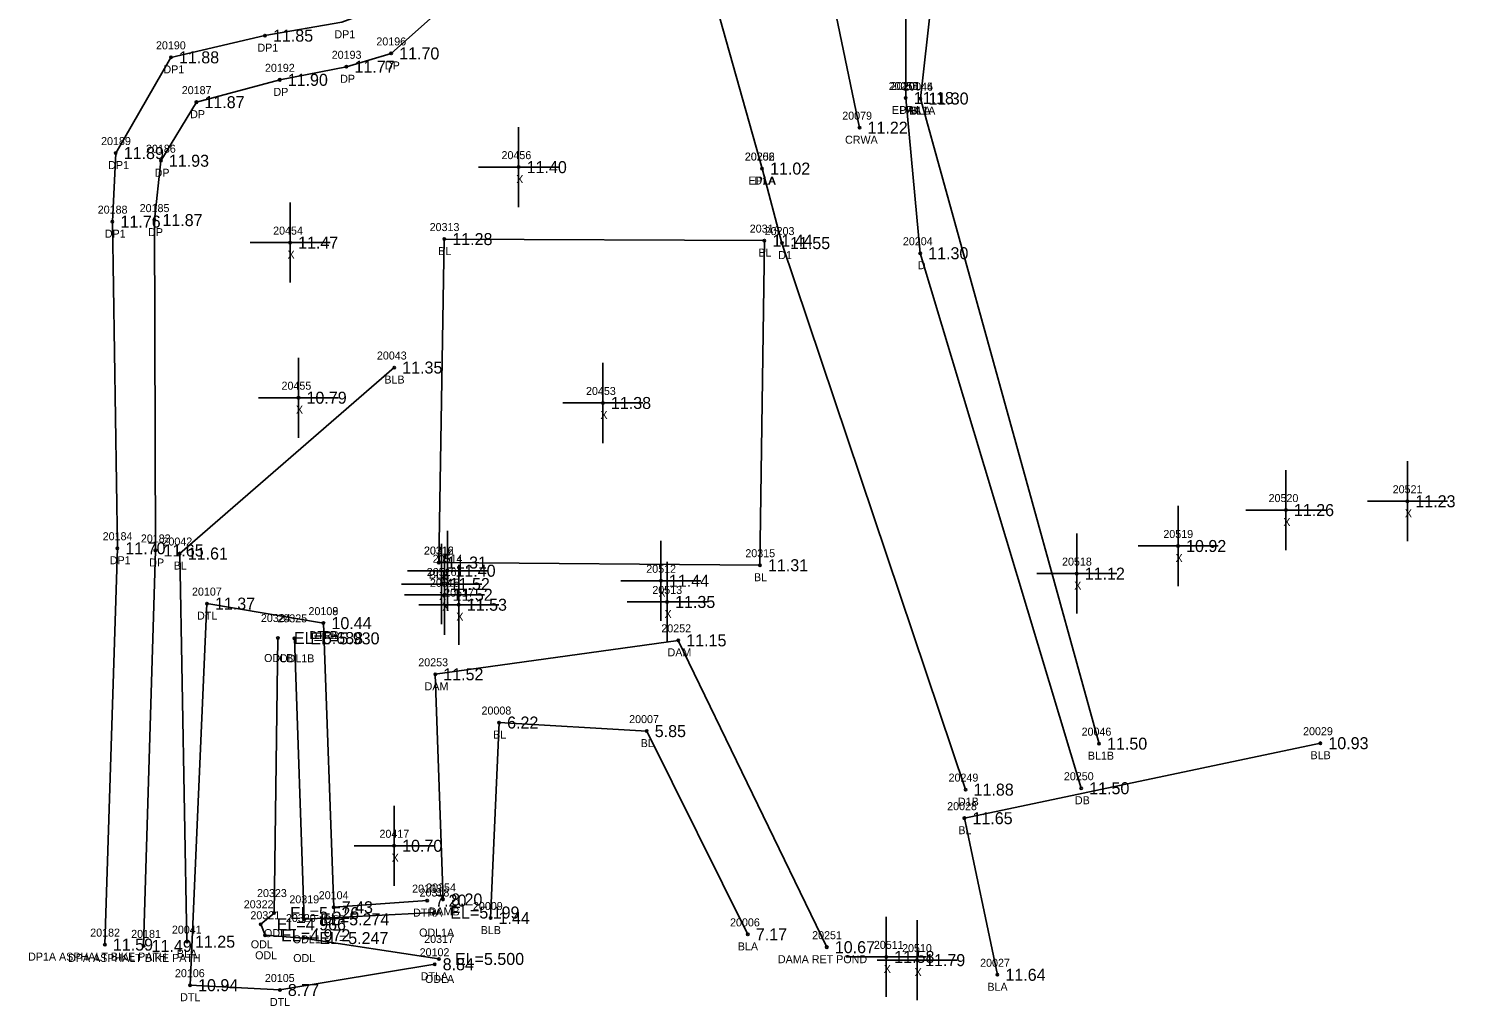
# Model space of a CAD drawing. Extents: x 2072302 to 2072980, y 127650 to 129736.
# Drawn here: x 2072679.9 to 2072860.8, y 128232.2 to 128354.3 of the extents above; entities that cross this region are included whole.
import ezdxf

# ---------------------------------------------------------------- set-up
doc = ezdxf.new("R2010")
doc.units = 0
for name, color, linetype in [('RD_DTM_BkLn1', 7, 'Continuous'), ('RD_DTM_BkLn_txCode', 7, 'Continuous'), ('RD_EX_Dam', 7, 'Continuous'), ('RD_EX_Dam_txCode', 7, 'Continuous'), ('RD_EX_Driveway', 7, 'Continuous'), ('RD_EX_Driveway_txCode', 7, 'Continuous'), ('RD_EX_H2O', 7, 'Continuous'), ('RD_EX_H2O_txCode', 7, 'Continuous'), ('RD_EX_Misc', 7, 'Continuous'), ('RD_EX_Misc_txCode', 7, 'Continuous'), ('RD_EX_Road', 7, 'Continuous'), ('RD_EX_Road_txCode', 7, 'Continuous'), ('RD_EX_TX_Dam_ELEV', 7, 'Continuous'), ('RD_EX_TX_Driveway_ELEV', 7, 'Continuous'), ('RD_EX_TX_H2O_ELEV', 7, 'Continuous'), ('RD_EX_TX_Misc_ELEV', 7, 'Continuous'), ('RD_EX_TX_Road_ELEV', 7, 'Continuous'), ('RD_HC_Survey_ELEV', 7, 'Continuous'), ('RD_HC_Survey_txCode', 7, 'Continuous'), ('RD_SMD_Locator', 7, 'Continuous')]:
    doc.layers.add(name, color=color, linetype=linetype)

msp = doc.modelspace()

# ---------------------------------------------------------------- linework, layer by layer
at = {"layer": 'RD_DTM_BkLn1'}
msp.add_line((2072791.29, 128345.62), (2072813.61, 128265.01), dxfattribs=at)
for points in [[(2072783.68, 128341.98), (2072775.38, 128381.91), (2072773.13, 128410.46), (2072778.13, 128436.13), (2072789.72, 128460.89), (2072826.62, 128532.44), (2072863.13, 128603.15), (2072886.77, 128648.23), (2072893.1, 128661.91)], [(2072791.29, 128345.62), (2072800.72, 128429.53), (2072808.9, 128452.58), (2072870.32, 128568.64), (2072876.57, 128573.6), (2072916.77, 128564.68), (2072920.97, 128548.67)], [(2072731.1, 128287.64), (2072731.79, 128328.06), (2072771.79, 128327.87), (2072771.24, 128287.31), (2072731.1, 128287.64)], [(2072699.63, 128240.27), (2072698.73, 128288.77), (2072725.53, 128312.01)], [(2072769.72, 128241.18), (2072757.09, 128266.58), (2072738.64, 128267.65), (2072737.57, 128243.22)], [(2072800.91, 128236.13), (2072796.79, 128255.7), (2072841.27, 128265.07)]]:
    msp.add_lwpolyline(points, dxfattribs=at)
at = {"layer": 'RD_EX_Dam'}
msp.add_lwpolyline([(2072779.59, 128239.58), (2072761.03, 128277.92), (2072730.66, 128273.68), (2072731.64, 128245.54)], dxfattribs=at)
at = {"layer": 'RD_EX_Driveway'}
for points in [[(2072689.37, 128239.9), (2072690.93, 128289.43), (2072690.32, 128330.24), (2072690.73, 128338.81), (2072697.63, 128350.77), (2072709.38, 128353.48), (2072719, 128355.15), (2072723.52, 128356.83), (2072727.18, 128360.82), (2072729.07, 128366.04), (2072736.87, 128415.65), (2072743.44, 128446.63), (2072749.73, 128459.37), (2072755.76, 128468.63), (2072761.76, 128476.56), (2072776.61, 128495.01), (2072792.09, 128518.96), (2072805.19, 128542.59), (2072810.66, 128554.44), (2072797.46, 128551.01)], [(2072694.21, 128239.74), (2072695.7, 128289.15), (2072695.56, 128330.43), (2072696.37, 128337.85), (2072700.81, 128345.17), (2072711.22, 128347.96), (2072719.56, 128349.59), (2072725.15, 128351.26), (2072733.07, 128358.33), (2072734.19, 128365.42), (2072741.79, 128414.16), (2072748.82, 128445.27), (2072754.15, 128456.57), (2072759.92, 128465.41), (2072766.21, 128473.75), (2072780.47, 128491.8), (2072796.27, 128516), (2072809.9, 128540.1), (2072821.01, 128555.78)], [(2072789.45, 128345.69), (2072791.26, 128326.29), (2072811.38, 128259.44)], [(2072771.5, 128336.87), (2072773.99, 128327.56), (2072796.93, 128259.27)]]:
    msp.add_lwpolyline(points, dxfattribs=at)
at = {"layer": 'RD_EX_H2O'}
for points in [[(2072730.59, 128237.45), (2072711.24, 128234.23), (2072700.02, 128234.83), (2072702.13, 128282.51), (2072716.69, 128280.07)], [(2072729.65, 128245.4), (2072717.97, 128244.57), (2072716.69, 128280.07)], [(2072731.12, 128238.11), (2072714.16, 128240.72), (2072709.4, 128241.07), (2072708.85, 128242.44), (2072710.51, 128243.84), (2072710.99, 128278.21)], [(2072730.54, 128243.91), (2072714.27, 128243.06), (2072713.05, 128278.17)]]:
    msp.add_lwpolyline(points, dxfattribs=at)
at = {"layer": 'RD_EX_Misc'}
for p, q in [((2072741.08, 128332.05), (2072741.08, 128342.05)), ((2072736.08, 128337.05), (2072746.08, 128337.05)), ((2072712.52, 128322.62), (2072712.52, 128332.62)), ((2072707.52, 128327.62), (2072717.52, 128327.62)), ((2072713.57, 128303.24), (2072713.57, 128313.24)), ((2072751.61, 128302.58), (2072751.61, 128312.58)), ((2072708.57, 128308.24), (2072718.57, 128308.24)), ((2072746.61, 128307.58), (2072756.61, 128307.58)), ((2072836.96, 128289.2), (2072836.96, 128299.2)), ((2072852.14, 128290.3), (2072852.14, 128300.3)), ((2072847.14, 128295.3), (2072857.14, 128295.3)), ((2072823.49, 128284.71), (2072823.49, 128294.71)), ((2072831.96, 128294.2), (2072841.96, 128294.2)), ((2072731.46, 128279.96), (2072731.46, 128289.96)), ((2072732.18, 128281.62), (2072732.18, 128291.62)), ((2072758.86, 128280.36), (2072758.86, 128290.36)), ((2072810.82, 128281.26), (2072810.82, 128291.26)), ((2072731.82, 128278.61), (2072731.82, 128288.61)), ((2072818.49, 128289.71), (2072828.49, 128289.71)), ((2072727.18, 128286.62), (2072737.18, 128286.62)), ((2072733.6, 128277.37), (2072733.6, 128287.37)), ((2072759.63, 128277.72), (2072759.63, 128287.72)), ((2072805.82, 128286.26), (2072815.82, 128286.26)), ((2072726.46, 128284.96), (2072736.46, 128284.96)), ((2072753.86, 128285.36), (2072763.86, 128285.36)), ((2072726.82, 128283.61), (2072736.82, 128283.61)), ((2072754.63, 128282.72), (2072764.63, 128282.72)), ((2072728.6, 128282.37), (2072738.6, 128282.37)), ((2072725.52, 128247.25), (2072725.52, 128257.25)), ((2072720.52, 128252.25), (2072730.52, 128252.25)), ((2072787.02, 128233.37), (2072787.02, 128243.37)), ((2072790.87, 128232.96), (2072790.87, 128242.96)), ((2072782.02, 128238.37), (2072792.02, 128238.37)), ((2072785.87, 128237.96), (2072795.87, 128237.96))]:
    msp.add_line(p, q, dxfattribs=at)
at = {"layer": 'RD_EX_Road'}
for points in [[(2072789.45, 128345.69), (2072789.46, 128382.93), (2072788.01, 128408.09), (2072794.06, 128431.26), (2072804.3, 128453.88), (2072840.7, 128525.64), (2072876.68, 128596.08), (2072888.72, 128617.36), (2072893.24, 128622.62), (2072899.84, 128627.36), (2072910.72, 128631.76), (2072918.79, 128632.23), (2072935.82, 128627.02), (2072957.37, 128619.98)], [(2072771.5, 128336.87), (2072760.1, 128377.44), (2072757.11, 128412.49), (2072764.76, 128439.95), (2072775.68, 128466.69), (2072812.91, 128539.86)]]:
    msp.add_lwpolyline(points, dxfattribs=at)
at = {"layer": 'RD_SMD_Locator'}
for centre in [(2072709.38, 128353.48), (2072725.15, 128351.26), (2072697.63, 128350.77), (2072719.56, 128349.59), (2072711.22, 128347.96), (2072700.81, 128345.17), (2072789.45, 128345.69), (2072789.45, 128345.69), (2072791.29, 128345.62), (2072791.29, 128345.62), (2072783.68, 128341.98), (2072690.73, 128338.81), (2072696.37, 128337.85), (2072741.08, 128337.05), (2072771.5, 128336.87), (2072771.5, 128336.87), (2072690.32, 128330.24), (2072695.56, 128330.43), (2072731.79, 128328.06), (2072771.79, 128327.87), (2072712.52, 128327.62), (2072773.99, 128327.56), (2072791.26, 128326.29), (2072725.53, 128312.01), (2072713.57, 128308.24), (2072751.61, 128307.58), (2072852.14, 128295.3), (2072836.96, 128294.2), (2072690.93, 128289.43), (2072695.7, 128289.15), (2072698.73, 128288.77), (2072823.49, 128289.71), (2072731.1, 128287.64), (2072731.1, 128287.64), (2072732.18, 128286.62), (2072771.24, 128287.31), (2072810.82, 128286.26), (2072731.46, 128284.96), (2072758.86, 128285.36), (2072702.13, 128282.51), (2072731.82, 128283.61), (2072759.63, 128282.72), (2072733.6, 128282.37), (2072716.69, 128280.07), (2072716.69, 128280.07), (2072710.99, 128278.21), (2072713.05, 128278.17), (2072761.03, 128277.92), (2072730.66, 128273.68), (2072738.64, 128267.65), (2072757.09, 128266.58), (2072813.61, 128265.01), (2072841.27, 128265.07), (2072796.93, 128259.27), (2072811.38, 128259.44), (2072796.79, 128255.7), (2072725.52, 128252.25), (2072717.97, 128244.57), (2072729.65, 128245.4), (2072731.64, 128245.54), (2072710.51, 128243.84), (2072714.27, 128243.06), (2072730.54, 128243.91), (2072737.57, 128243.22), (2072708.85, 128242.44), (2072709.4, 128241.07), (2072769.72, 128241.18), (2072689.37, 128239.9), (2072694.21, 128239.74), (2072699.63, 128240.27), (2072714.16, 128240.72), (2072779.59, 128239.58), (2072730.59, 128237.45), (2072731.12, 128238.11), (2072787.02, 128238.37), (2072790.87, 128237.96), (2072800.91, 128236.13), (2072700.02, 128234.83), (2072711.24, 128234.23)]:
    msp.add_circle(centre, 0.15, dxfattribs=at)

# ---------------------------------------------------------------- texts
at = {"layer": 'RD_DTM_BkLn_txCode'}
for s, p in [('20044', (2072789.14, 128346.62)), ('20045', (2072789.14, 128346.62)), ('BL1A', (2072789.88, 128343.62)), ('BLA', (2072790.05, 128343.62)), ('20313', (2072729.96, 128329.06)), ('20314', (2072769.96, 128328.87)), ('BL', (2072731.03, 128326.06)), ('BL', (2072771.04, 128325.87)), ('20043', (2072723.37, 128313.01)), ('BLB', (2072724.3, 128310.01)), ('20042', (2072696.57, 128289.77)), ('20316', (2072729.24, 128288.64)), ('20312', (2072729.26, 128288.64)), ('20315', (2072769.41, 128288.31)), ('BL', (2072697.97, 128286.77)), ('BLA', (2072729.85, 128285.64)), ('BLB', (2072729.87, 128285.64)), ('BL', (2072770.49, 128285.31)), ('20008', (2072736.44, 128268.65)), ('20007', (2072754.89, 128267.58)), ('BL', (2072737.89, 128265.65)), ('20046', (2072811.43, 128266.01)), ('20029', (2072839.11, 128266.07)), ('BL', (2072756.33, 128264.58)), ('BL1B', (2072812.21, 128263.01)), ('BLB', (2072840.04, 128263.07)), ('20028', (2072794.63, 128256.7)), ('BL', (2072796.03, 128253.7)), ('20009', (2072735.37, 128244.22)), ('20006', (2072767.5, 128242.18)), ('20041', (2072697.75, 128241.27)), ('BLB', (2072736.34, 128241.22)), ('BLA', (2072698.38, 128238.27)), ('BLA', (2072768.47, 128239.18)), ('20027', (2072798.75, 128237.13)), ('BLA', (2072799.66, 128234.13))]:
    msp.add_text(s, height=1, dxfattribs=at).set_placement(p)
at = {"layer": 'RD_EX_Dam_txCode'}
for s, p in [('20252', (2072758.91, 128278.92)), ('20253', (2072728.54, 128274.68)), ('DAM', (2072759.69, 128275.92)), ('DAM', (2072729.33, 128271.68)), ('20254', (2072729.52, 128246.54)), ('DAMB', (2072729.84, 128243.54)), ('20251', (2072777.76, 128240.58)), ('DAMA RET POND', (2072773.48, 128237.58))]:
    msp.add_text(s, height=1, dxfattribs=at).set_placement(p)
at = {"layer": 'RD_EX_Driveway_txCode'}
for s, p in [('DP1', (2072718.06, 128353.15)), ('20196', (2072723.3, 128352.26)), ('20190', (2072695.76, 128351.77)), ('DP1', (2072708.44, 128351.48)), ('20193', (2072717.72, 128350.59)), ('DP1', (2072696.69, 128348.77)), ('20192', (2072709.38, 128348.96)), ('DP', (2072724.37, 128349.26)), ('DP', (2072718.78, 128347.59)), ('20187', (2072698.98, 128346.17)), ('DP', (2072710.44, 128345.96)), ('20201', (2072787.57, 128346.69)), ('DP', (2072700.03, 128343.17)), ('DA', (2072788.65, 128343.69)), ('20189', (2072688.9, 128339.81)), ('20186', (2072694.51, 128338.85)), ('20202', (2072769.34, 128337.87)), ('DP1', (2072689.79, 128336.81)), ('DP', (2072695.59, 128335.85)), ('D1A', (2072770.54, 128334.87)), ('20188', (2072688.48, 128331.24)), ('20185', (2072693.72, 128331.43)), ('DP1', (2072689.37, 128328.24)), ('DP', (2072694.78, 128328.43)), ('20203', (2072771.83, 128328.56)), ('20204', (2072789.1, 128327.29)), ('D1', (2072773.52, 128325.56)), ('D', (2072790.95, 128324.29)), ('20184', (2072689.1, 128290.43)), ('20183', (2072693.87, 128290.15)), ('DP1', (2072689.99, 128287.43)), ('DP', (2072694.92, 128287.15)), ('20249', (2072794.81, 128260.27)), ('20250', (2072809.22, 128260.44)), ('D1B', (2072795.98, 128257.27)), ('DB', (2072810.6, 128257.44)), ('20182', (2072687.54, 128240.9)), ('20181', (2072692.66, 128240.74)), ('DP1A ASPHALT BIKE PATH', (2072679.78, 128237.9)), ('DPA ASPHALT BIKE PATH', (2072684.77, 128237.74))]:
    msp.add_text(s, height=1, dxfattribs=at).set_placement(p)
at = {"layer": 'RD_EX_H2O_txCode'}
for s, p in [('20107', (2072700.26, 128283.51)), ('DTL', (2072700.89, 128280.51)), ('20324', (2072708.87, 128280.21)), ('20325', (2072710.93, 128280.17)), ('20108', (2072714.82, 128281.07)), ('20109', (2072714.82, 128281.07)), ('DTRB', (2072714.95, 128278.07)), ('DTLB', (2072714.97, 128278.07)), ('ODLB', (2072709.27, 128275.21)), ('ODL1B', (2072711.17, 128275.17)), ('20323', (2072708.39, 128245.84)), ('20104', (2072716.1, 128245.57)), ('20103', (2072727.77, 128246.4)), ('20318', (2072728.7, 128245.91)), ('20322', (2072706.73, 128244.44)), ('20319', (2072712.43, 128245.06)), ('20321', (2072707.56, 128243.07)), ('20320', (2072712, 128242.72)), ('DTR', (2072716.7, 128242.57)), ('DTRA', (2072727.89, 128243.4)), ('ODL', (2072709.26, 128240.84)), ('ODL1', (2072712.86, 128240.06)), ('ODL1A', (2072728.64, 128240.91)), ('20317', (2072729.28, 128240.11)), ('ODL', (2072707.61, 128239.44)), ('20102', (2072728.71, 128238.45)), ('ODL', (2072708.15, 128238.07)), ('ODL', (2072712.91, 128237.72)), ('20106', (2072698.13, 128235.83)), ('20105', (2072709.37, 128235.23)), ('DTLA', (2072728.85, 128235.45)), ('ODLA', (2072729.38, 128235.11)), ('DTL', (2072698.78, 128232.83)), ('DTL', (2072710, 128232.23))]:
    msp.add_text(s, height=1, dxfattribs=at).set_placement(p)
at = {"layer": 'RD_EX_Misc_txCode'}
for s, p in [('20456', (2072738.94, 128338.05)), ('X', (2072740.77, 128335.05)), ('20454', (2072710.4, 128328.62)), ('X', (2072712.2, 128325.62)), ('20455', (2072711.45, 128309.24)), ('20453', (2072749.5, 128308.58)), ('X', (2072713.25, 128306.24)), ('X', (2072751.3, 128305.58)), ('20521', (2072850.31, 128296.3)), ('20520', (2072834.8, 128295.2)), ('X', (2072851.83, 128293.3)), ('20519', (2072821.65, 128290.71)), ('X', (2072836.64, 128292.2)), ('20514', (2072730.34, 128287.62)), ('20518', (2072808.99, 128287.26)), ('X', (2072823.17, 128287.71)), ('20516', (2072729.6, 128285.96)), ('20512', (2072757.03, 128286.36)), ('20515', (2072729.99, 128284.61)), ('X', (2072731.86, 128284.62)), ('20513', (2072757.79, 128283.72)), ('X', (2072810.51, 128284.26)), ('X', (2072731.14, 128282.96)), ('20517', (2072731.77, 128283.37)), ('X', (2072758.55, 128283.36)), ('X', (2072731.51, 128281.61)), ('X', (2072733.29, 128280.37)), ('X', (2072759.31, 128280.72)), ('20417', (2072723.69, 128253.25)), ('X', (2072725.21, 128250.25)), ('20511', (2072785.47, 128239.37)), ('20510', (2072789, 128238.96)), ('X', (2072786.71, 128236.37)), ('X', (2072790.56, 128235.96))]:
    msp.add_text(s, height=1, dxfattribs=at).set_placement(p)
at = {"layer": 'RD_EX_Road_txCode'}
for s, p in [('20255', (2072787.33, 128346.69)), ('EPRA', (2072787.73, 128343.69)), ('20256', (2072769.36, 128337.87)), ('EPLA', (2072769.81, 128334.87))]:
    msp.add_text(s, height=1, dxfattribs=at).set_placement(p)
at = {"layer": 'RD_EX_TX_Dam_ELEV'}
for s, p in [('11.15', (2072762.03, 128277.17)), ('11.52', (2072731.66, 128272.93)), ('8.20', (2072732.64, 128244.79)), ('10.67', (2072780.59, 128238.83))]:
    msp.add_text(s, height=1.5, dxfattribs=at).set_placement(p)
at = {"layer": 'RD_EX_TX_Driveway_ELEV'}
for s, p in [('11.85', (2072710.38, 128352.73)), ('11.88', (2072698.63, 128350.02)), ('11.70', (2072726.15, 128350.51)), ('11.77', (2072720.56, 128348.84)), ('11.90', (2072712.22, 128347.21)), ('11.18', (2072790.45, 128344.94)), ('11.87', (2072701.81, 128344.42)), ('11.89', (2072691.73, 128338.06)), ('11.93', (2072697.37, 128337.1)), ('11.02', (2072772.5, 128336.12)), ('11.76', (2072691.32, 128329.49)), ('11.87', (2072696.56, 128329.68)), ('11.55', (2072774.99, 128326.81)), ('11.30', (2072792.26, 128325.54)), ('11.70', (2072691.93, 128288.68)), ('11.65', (2072696.7, 128288.4)), ('11.88', (2072797.93, 128258.52)), ('11.50', (2072812.38, 128258.69)), ('11.59', (2072690.37, 128239.15)), ('11.49', (2072695.21, 128238.99))]:
    msp.add_text(s, height=1.5, dxfattribs=at).set_placement(p)
at = {"layer": 'RD_EX_TX_H2O_ELEV'}
for s, p in [('11.37', (2072703.13, 128281.76)), ('10.44', (2072717.69, 128279.32)), ('10.44', (2072717.69, 128279.32)), ('EL=5.688', (2072712.99, 128277.46)), ('EL=5.930', (2072715.05, 128277.42)), ('7.43', (2072718.97, 128243.82)), ('7.20', (2072730.65, 128244.65)), ('EL=5.199', (2072732.54, 128243.16)), ('EL=4.966', (2072710.85, 128241.69)), ('EL=5.526', (2072712.51, 128243.09)), ('EL=5.274', (2072716.27, 128242.31)), ('EL=4.972', (2072711.4, 128240.32)), ('EL=5.247', (2072716.16, 128239.97)), ('8.84', (2072731.59, 128236.7)), ('EL=5.500', (2072733.12, 128237.36)), ('10.94', (2072701.02, 128234.08)), ('8.77', (2072712.24, 128233.48))]:
    msp.add_text(s, height=1.5, dxfattribs=at).set_placement(p)
at = {"layer": 'RD_EX_TX_Misc_ELEV'}
for s, p in [('11.30', (2072792.29, 128344.87)), ('11.30', (2072792.29, 128344.87)), ('11.40', (2072742.08, 128336.3)), ('11.47', (2072713.52, 128326.87)), ('11.28', (2072732.79, 128327.31)), ('11.44', (2072772.79, 128327.12)), ('11.35', (2072726.53, 128311.26)), ('10.79', (2072714.57, 128307.49)), ('11.38', (2072752.61, 128306.83)), ('11.23', (2072853.14, 128294.55)), ('11.26', (2072837.96, 128293.45)), ('10.92', (2072824.49, 128288.96)), ('11.61', (2072699.73, 128288.02)), ('11.31', (2072732.1, 128286.89)), ('11.31', (2072732.1, 128286.89)), ('11.31', (2072772.24, 128286.56)), ('11.40', (2072733.18, 128285.87)), ('11.12', (2072811.82, 128285.51)), ('11.52', (2072732.46, 128284.21)), ('11.44', (2072759.86, 128284.61)), ('11.52', (2072732.82, 128282.86)), ('11.53', (2072734.6, 128281.62)), ('11.35', (2072760.63, 128281.97)), ('6.22', (2072739.64, 128266.9)), ('5.85', (2072758.09, 128265.83)), ('11.50', (2072814.61, 128264.26)), ('10.93', (2072842.27, 128264.32)), ('11.65', (2072797.79, 128254.95)), ('10.70', (2072726.52, 128251.5)), ('1.44', (2072738.57, 128242.47)), ('11.25', (2072700.63, 128239.52)), ('7.17', (2072770.72, 128240.43)), ('11.58', (2072788.02, 128237.62)), ('11.79', (2072791.87, 128237.21)), ('11.64', (2072801.91, 128235.38))]:
    msp.add_text(s, height=1.5, dxfattribs=at).set_placement(p)
at = {"layer": 'RD_EX_TX_Road_ELEV'}
for s, p in [('11.18', (2072790.45, 128344.94)), ('11.02', (2072772.5, 128336.12))]:
    msp.add_text(s, height=1.5, dxfattribs=at).set_placement(p)
at = {"layer": 'RD_HC_Survey_ELEV'}
msp.add_text('11.22', height=1.5, dxfattribs=at).set_placement((2072784.68, 128341.23))
at = {"layer": 'RD_HC_Survey_txCode'}
for s, p in [('20079', (2072781.52, 128342.98)), ('CRWA', (2072781.87, 128339.98))]:
    msp.add_text(s, height=1, dxfattribs=at).set_placement(p)

doc.saveas('drawing.dxf')
